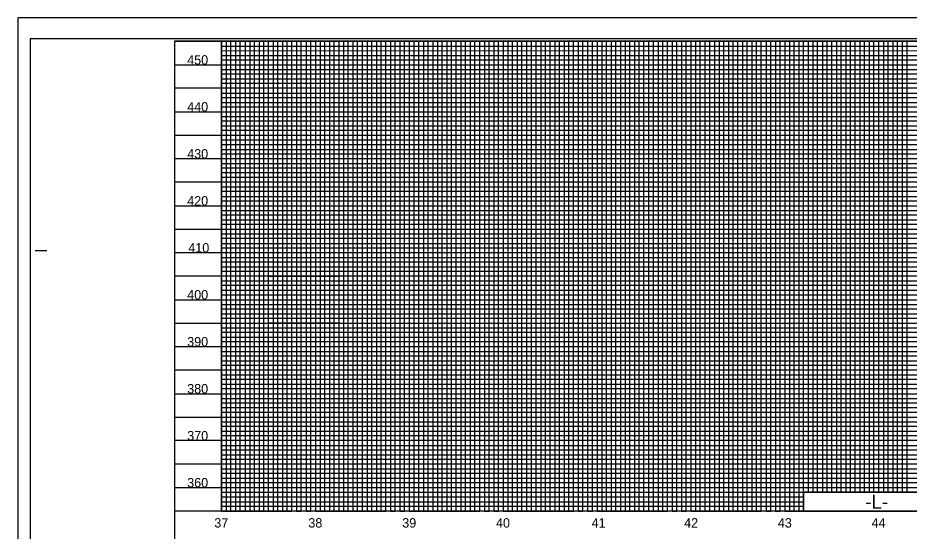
# Model space of a CAD drawing. Extents: x 1632687 to 1634895, y 1174336 to 1175436.
# Drawn here: x 1632687 to 1633637, y 1174889 to 1175436 of the extents above; entities that cross this region are included whole.
import ezdxf

# ---------------------------------------------------------------- set-up
doc = ezdxf.new("R2010")
doc.units = 0
for name, color, linetype in [('Exist Vertical Profile Horizontal Axis Label Major', 7, 'Continuous'), ('Exist Vertical Profile Vertical Axis Label', 7, 'Continuous'), ('Prop Grid Mask', 7, 'Continuous'), ('Sheet Data Field CELL', 7, 'Continuous'), ('Sheet Layout Profile Border Port 1', 7, 'Continuous'), ('Sheet Plot Border Inside CELL', 7, 'Continuous'), ('Sheet Plot Border Outside CELL', 7, 'Continuous'), ('Sheet Profile CELL', 7, 'Continuous'), ('Sheet Profile Grid Major CELL', 7, 'Continuous'), ('Sheet Profile Grid Middle CELL', 7, 'Continuous'), ('Sheet Profile Grid Minor CELL', 7, 'Continuous')]:
    doc.layers.add(name, color=color, linetype=linetype)

msp = doc.modelspace()

# ---------------------------------------------------------------- linework, layer by layer
at = {"layer": 'Prop Grid Mask'}
msp.add_lwpolyline([(1632954.31, 1175160.79), (1633029.31, 1175160.79), (1633029.31, 1175110.79), (1632954.31, 1175110.79)], close=True, dxfattribs=at)
at = {"layer": 'Sheet Data Field CELL'}
msp.add_lwpolyline([(1633524.31, 1174910.79), (1633684.31, 1174910.79), (1633684.31, 1174930.79), (1633524.31, 1174930.79)], close=True, dxfattribs=at)
at = {"layer": 'Sheet Layout Profile Border Port 1'}
msp.add_lwpolyline([(1632904.31, 1175410.79), (1633954.21, 1175410.79), (1633954.21, 1175384.53), (1634154.26, 1175384.53), (1634154.26, 1175249.74), (1634304.31, 1175249.74), (1634304.31, 1174935.79), (1634104.31, 1174935.79), (1634104.31, 1174910.79), (1633684.31, 1174910.79), (1633684.31, 1174930.79), (1633524.31, 1174930.79), (1633524.31, 1174910.79), (1632904.31, 1174910.79)], close=True, dxfattribs=at)
at = {"layer": 'Sheet Plot Border Inside CELL'}
msp.add_lwpolyline([(1632700.31, 1174358.24), (1634366.81, 1174358.24), (1634366.81, 1175413.34), (1632700.31, 1175413.34)], close=True, dxfattribs=at)
at = {"layer": 'Sheet Plot Border Outside CELL'}
msp.add_lwpolyline([(1632687.31, 1174335.79), (1634371.31, 1174335.79), (1634371.31, 1175435.79), (1632687.31, 1175435.79)], close=True, dxfattribs=at)
at = {"layer": 'Sheet Profile CELL'}
for p, q in [((1632705.81, 1175188.29), (1632718.31, 1175188.29)), ((1634354.31, 1174910.79), (1632854.31, 1174910.79))]:
    msp.add_line(p, q, dxfattribs=at)
msp.add_lwpolyline([(1634354.31, 1175410.79), (1632854.31, 1175410.79), (1632854.31, 1174360.79), (1634354.31, 1174360.79)], close=True, dxfattribs=at)
at = {"layer": 'Sheet Profile Grid Major CELL'}
for p, q in [((1632904.31, 1175410.79), (1632904.31, 1174910.79)), ((1632954.31, 1174910.79), (1632954.31, 1175410.79)), ((1632954.31, 1175410.79), (1633004.31, 1175410.79)), ((1633004.31, 1175410.79), (1633004.31, 1174910.79)), ((1633054.31, 1174910.79), (1633054.31, 1175410.79)), ((1633054.31, 1175410.79), (1633104.31, 1175410.79)), ((1633104.31, 1175410.79), (1633104.31, 1174910.79)), ((1633154.31, 1174910.79), (1633154.31, 1175410.79)), ((1633154.31, 1175410.79), (1633204.31, 1175410.79)), ((1633204.31, 1175410.79), (1633204.31, 1174910.79)), ((1633254.31, 1174910.79), (1633254.31, 1175410.79)), ((1633254.31, 1175410.79), (1633304.31, 1175410.79)), ((1633304.31, 1175410.79), (1633304.31, 1174910.79)), ((1633354.31, 1174910.79), (1633354.31, 1175410.79)), ((1633354.31, 1175410.79), (1633404.31, 1175410.79)), ((1633404.31, 1175410.79), (1633404.31, 1174910.79)), ((1633454.31, 1174910.79), (1633454.31, 1175410.79)), ((1633454.31, 1175410.79), (1633504.31, 1175410.79)), ((1633504.31, 1175410.79), (1633504.31, 1174910.79)), ((1633554.31, 1174930.79), (1633554.31, 1175410.79)), ((1633554.31, 1175410.79), (1633604.31, 1175410.79)), ((1633604.31, 1175410.79), (1633604.31, 1174930.79)), ((1632904.31, 1174910.79), (1632954.31, 1174910.79)), ((1633004.31, 1174910.79), (1633054.31, 1174910.79)), ((1633104.31, 1174910.79), (1633154.31, 1174910.79)), ((1633204.31, 1174910.79), (1633254.31, 1174910.79)), ((1633304.31, 1174910.79), (1633354.31, 1174910.79)), ((1633404.31, 1174910.79), (1633454.31, 1174910.79)), ((1633504.31, 1174910.79), (1633534.31, 1174910.79))]:
    msp.add_line(p, q, dxfattribs=at)
for points in [[(1632854.31, 1175385.79), (1633954.21, 1175385.79)], [(1632854.31, 1175335.79), (1634154.26, 1175335.79)], [(1634154.26, 1175285.79), (1632854.31, 1175285.79), (1632854.31, 1175235.79), (1634354.31, 1175235.79)], [(1634354.31, 1175185.79), (1632854.31, 1175185.79), (1632854.31, 1175135.79), (1634354.31, 1175135.79)], [(1634354.31, 1175085.79), (1632854.31, 1175085.79), (1632854.31, 1175035.79), (1634354.31, 1175035.79)], [(1634354.31, 1174985.79), (1632854.31, 1174985.79), (1632854.31, 1174985.79), (1632854.31, 1174935.79), (1634354.31, 1174935.79)]]:
    msp.add_lwpolyline(points, dxfattribs=at)
at = {"layer": 'Sheet Profile Grid Middle CELL'}
msp.add_line((1632854.31, 1175410.79), (1633954.21, 1175410.79), dxfattribs=at)
for points in [[(1632929.31, 1175410.79), (1632929.31, 1174910.79), (1632979.31, 1174910.79), (1632979.31, 1175410.79), (1633029.31, 1175410.79), (1633029.31, 1174910.79), (1633079.31, 1174910.79), (1633079.31, 1175410.79), (1633129.31, 1175410.79), (1633129.31, 1174910.79), (1633179.31, 1174910.79), (1633179.31, 1175410.79), (1633229.31, 1175410.79), (1633229.31, 1174910.79), (1633279.31, 1174910.79), (1633279.31, 1175410.79), (1633329.31, 1175410.79), (1633329.31, 1174910.79), (1633379.31, 1174910.79), (1633379.31, 1175410.79), (1633429.31, 1175410.79), (1633429.31, 1174910.79), (1633479.31, 1174910.79), (1633479.31, 1174910.79), (1633479.31, 1175410.79), (1633529.31, 1175410.79), (1633529.31, 1174930.79)], [(1633579.31, 1174930.79), (1633579.31, 1175410.79), (1633629.31, 1175410.79), (1633629.31, 1174930.79)], [(1634154.26, 1175360.79), (1632854.31, 1175360.79), (1632854.31, 1175310.79), (1634154.26, 1175310.79)], [(1634154.26, 1175260.79), (1632854.31, 1175260.79), (1632854.31, 1175210.79), (1634354.31, 1175210.79)], [(1634354.31, 1175160.79), (1632854.31, 1175160.79), (1632854.31, 1175110.79), (1634354.31, 1175110.79)], [(1634354.31, 1175060.79), (1632854.31, 1175060.79), (1632854.31, 1175010.79), (1634354.31, 1175010.79)], [(1634354.31, 1174960.79), (1632854.31, 1174960.79)]]:
    msp.add_lwpolyline(points, dxfattribs=at)
at = {"layer": 'Sheet Profile Grid Minor CELL'}
for p, q in [((1632904.31, 1175405.79), (1633954.21, 1175405.79)), ((1633434.31, 1175410.79), (1633434.31, 1174910.79)), ((1633439.31, 1174910.79), (1633439.31, 1175410.79)), ((1633439.31, 1175410.79), (1633444.31, 1175410.79)), ((1633444.31, 1175410.79), (1633444.31, 1174910.79)), ((1633449.31, 1174910.79), (1633449.31, 1175410.79)), ((1633449.31, 1175410.79), (1633459.31, 1175410.79)), ((1633459.31, 1175410.79), (1633459.31, 1174910.79)), ((1633464.31, 1174910.79), (1633464.31, 1175410.79)), ((1633464.31, 1175410.79), (1633469.31, 1175410.79)), ((1633469.31, 1175410.79), (1633469.31, 1174910.79)), ((1633474.31, 1174910.79), (1633474.31, 1175410.79)), ((1633474.31, 1175410.79), (1633484.31, 1175410.79)), ((1633484.31, 1175410.79), (1633484.31, 1174910.79)), ((1633489.31, 1174910.79), (1633489.31, 1175410.79)), ((1633489.31, 1175410.79), (1633494.31, 1175410.79)), ((1633494.31, 1175410.79), (1633494.31, 1174910.79)), ((1633499.31, 1174910.79), (1633499.31, 1175410.79)), ((1633499.31, 1175410.79), (1633509.31, 1175410.79)), ((1633509.31, 1175410.79), (1633509.31, 1174910.79)), ((1633514.31, 1174910.79), (1633514.31, 1175410.79)), ((1633514.31, 1175410.79), (1633519.31, 1175410.79)), ((1633519.31, 1175410.79), (1633519.31, 1174910.79)), ((1633524.31, 1174910.79), (1633524.31, 1175410.79)), ((1633524.31, 1175410.79), (1633534.31, 1175410.79)), ((1633534.31, 1175410.79), (1633534.31, 1174930.79)), ((1633539.31, 1174930.79), (1633539.31, 1175410.79)), ((1633539.31, 1175410.79), (1633544.31, 1175410.79)), ((1633544.31, 1175410.79), (1633544.31, 1174930.79)), ((1633549.31, 1174930.79), (1633549.31, 1175410.79)), ((1633549.31, 1175410.79), (1633559.31, 1175410.79)), ((1633559.31, 1175410.79), (1633559.31, 1174930.79)), ((1632904.31, 1175400.79), (1632904.31, 1175400.79)), ((1633954.21, 1175400.73), (1632904.31, 1175400.44)), ((1632904.31, 1175395.79), (1633954.21, 1175395.79)), ((1634154.31, 1175275.79), (1632904.31, 1175275.79)), ((1634154.31, 1175270.79), (1632904.31, 1175270.79)), ((1634154.31, 1175265.79), (1632904.31, 1175265.79)), ((1632904.31, 1175255.79), (1634154.31, 1175255.79)), ((1634154.31, 1175250.79), (1632904.31, 1175250.79)), ((1632904.31, 1175245.79), (1634304.31, 1175245.79)), ((1634304.31, 1175225.79), (1632904.31, 1175225.79)), ((1632904.31, 1175220.79), (1634304.31, 1175220.79)), ((1634304.31, 1175200.79), (1632904.31, 1175200.79)), ((1632904.31, 1175195.79), (1634304.31, 1175195.79)), ((1634304.31, 1175175.79), (1632904.31, 1175175.79)), ((1632904.31, 1175170.79), (1634304.31, 1175170.79)), ((1634304.31, 1175165.79), (1632904.31, 1175165.79)), ((1632904.31, 1175155.79), (1634304.31, 1175155.79)), ((1634304.31, 1175150.79), (1632904.31, 1175150.79)), ((1632904.31, 1175145.79), (1634304.31, 1175145.79)), ((1634304.31, 1175140.79), (1632904.31, 1175140.79)), ((1632904.31, 1175130.79), (1634304.31, 1175130.79)), ((1634304.31, 1175125.79), (1632904.31, 1175125.79)), ((1632904.31, 1175120.79), (1634304.31, 1175120.79)), ((1634304.31, 1175115.79), (1632904.31, 1175115.79)), ((1632904.31, 1175105.79), (1634304.31, 1175105.79)), ((1634304.31, 1175100.79), (1632904.31, 1175100.79)), ((1632904.31, 1175095.79), (1634304.31, 1175095.79)), ((1634304.31, 1175090.79), (1632904.31, 1175090.79)), ((1632904.31, 1175080.79), (1634304.31, 1175080.79)), ((1634304.31, 1175075.79), (1632904.31, 1175075.79)), ((1632904.31, 1175070.79), (1634304.31, 1175070.79)), ((1634304.31, 1175065.79), (1632904.31, 1175065.79)), ((1632904.31, 1175055.79), (1634304.31, 1175055.79)), ((1634304.31, 1175050.79), (1632904.31, 1175050.79)), ((1632904.31, 1175045.79), (1634304.31, 1175045.79)), ((1634304.31, 1175040.79), (1632904.31, 1175040.79)), ((1632904.31, 1175030.79), (1634304.31, 1175030.79)), ((1634304.31, 1175025.79), (1632904.31, 1175025.79)), ((1634304.31, 1175020.79), (1632904.31, 1175020.79)), ((1634304.31, 1175015.79), (1632904.31, 1175015.79)), ((1632904.31, 1175005.79), (1634304.31, 1175005.79)), ((1634304.31, 1175000.79), (1632904.31, 1175000.79)), ((1632904.31, 1174995.79), (1634304.31, 1174995.79)), ((1634304.31, 1174990.79), (1632904.31, 1174990.79)), ((1632904.31, 1174980.79), (1634304.31, 1174980.79)), ((1634304.31, 1174975.79), (1632904.31, 1174975.79)), ((1632904.31, 1174970.79), (1634304.31, 1174970.79)), ((1634304.31, 1174965.79), (1632904.31, 1174965.79)), ((1632904.31, 1174955.79), (1634304.31, 1174955.79)), ((1634304.31, 1174950.79), (1632904.31, 1174950.79)), ((1632904.31, 1174945.79), (1634304.31, 1174945.79)), ((1634304.31, 1174940.79), (1632904.31, 1174940.79)), ((1632904.31, 1174930.79), (1634104.31, 1174930.79)), ((1633524.31, 1174925.79), (1632904.31, 1174925.79)), ((1632904.31, 1174920.79), (1633524.31, 1174920.79)), ((1633434.31, 1174910.79), (1633439.31, 1174910.79)), ((1633444.31, 1174910.79), (1633449.31, 1174910.79)), ((1633459.31, 1174910.79), (1633464.31, 1174910.79)), ((1633469.31, 1174910.79), (1633474.31, 1174910.79)), ((1633484.31, 1174910.79), (1633489.31, 1174910.79)), ((1633494.31, 1174910.79), (1633499.31, 1174910.79)), ((1633509.31, 1174910.79), (1633514.31, 1174910.79)), ((1633519.31, 1174910.79), (1633524.31, 1174910.79)), ((1633534.31, 1174910.79), (1633539.31, 1174910.79)), ((1633544.31, 1174910.79), (1633549.31, 1174910.79))]:
    msp.add_line(p, q, dxfattribs=at)
for points in [[(1632909.31, 1175410.79), (1632909.31, 1174910.79), (1632914.31, 1174910.79), (1632914.31, 1175410.79), (1632919.31, 1175410.79), (1632919.31, 1174910.79), (1632924.31, 1174910.79), (1632924.31, 1175410.79), (1632934.31, 1175410.79), (1632934.31, 1174910.79), (1632939.31, 1174910.79), (1632939.31, 1175410.79), (1632944.31, 1175410.79), (1632944.31, 1174910.79), (1632949.31, 1174910.79), (1632959.31, 1174910.79), (1632964.31, 1174910.79), (1632964.31, 1175410.79), (1632969.31, 1175410.79), (1632969.31, 1174910.79), (1632974.31, 1174910.79), (1632974.31, 1175410.79), (1632984.31, 1175410.79), (1632984.31, 1174910.79), (1632989.31, 1174910.79), (1632989.31, 1175410.79), (1632994.31, 1175410.79), (1632994.31, 1174910.79), (1632999.31, 1174910.79), (1632999.31, 1175410.79), (1633009.31, 1175410.79), (1633009.31, 1174910.79), (1633014.31, 1174910.79), (1633014.31, 1175410.79), (1633019.31, 1175410.79), (1633019.31, 1174910.79), (1633024.31, 1174910.79), (1633024.31, 1175410.79), (1633034.31, 1175410.79), (1633034.31, 1174910.79), (1633039.31, 1174910.79), (1633039.31, 1175410.79), (1633044.31, 1175410.79), (1633044.31, 1174910.79), (1633049.31, 1174910.79), (1633049.31, 1175410.79), (1633059.31, 1175410.79), (1633059.31, 1174910.79), (1633064.31, 1174910.79), (1633064.31, 1175410.79), (1633069.31, 1175410.79), (1633069.31, 1174910.79), (1633074.31, 1174910.79), (1633074.31, 1175410.79), (1633084.31, 1175410.79), (1633084.31, 1174910.79), (1633089.31, 1174910.79), (1633089.31, 1175410.79), (1633094.31, 1175410.79), (1633094.31, 1174910.79), (1633099.31, 1174910.79), (1633099.31, 1175410.79), (1633109.31, 1175410.79), (1633109.31, 1174910.79), (1633114.31, 1174910.79), (1633114.31, 1175410.79), (1633119.31, 1175410.79), (1633119.31, 1174910.79)], [(1632949.31, 1174910.79), (1632949.31, 1175410.79), (1632959.31, 1175410.79), (1632959.31, 1174910.79)], [(1633119.31, 1174910.79), (1633124.31, 1174910.79), (1633124.31, 1175410.79), (1633134.31, 1175410.79), (1633134.31, 1174910.79), (1633139.31, 1174910.79), (1633139.31, 1175410.79), (1633144.31, 1175410.79), (1633144.31, 1174910.79), (1633149.31, 1174910.79), (1633149.31, 1175410.79), (1633159.31, 1175410.79), (1633159.31, 1174910.79), (1633164.31, 1174910.79), (1633164.31, 1175410.79), (1633169.31, 1175410.79), (1633169.31, 1174910.79), (1633174.31, 1174910.79), (1633174.31, 1175410.79), (1633184.31, 1175410.79), (1633184.31, 1174910.79), (1633189.31, 1174910.79), (1633189.31, 1175410.79), (1633194.31, 1175410.79), (1633194.31, 1174910.79), (1633199.31, 1174910.79), (1633199.31, 1175410.79), (1633209.31, 1175410.79), (1633209.31, 1174910.79), (1633214.31, 1174910.79), (1633214.31, 1175410.79), (1633219.31, 1175410.79), (1633219.31, 1174910.79), (1633224.31, 1174910.79), (1633224.31, 1175410.79), (1633234.31, 1175410.79), (1633234.31, 1174910.79), (1633239.31, 1174910.79), (1633239.31, 1175410.79), (1633244.31, 1175410.79), (1633244.31, 1174910.79), (1633249.31, 1174910.79), (1633249.31, 1175410.79), (1633259.31, 1175410.79), (1633259.31, 1174910.79), (1633264.31, 1174910.79), (1633264.31, 1175410.79), (1633269.31, 1175410.79), (1633269.31, 1174910.79), (1633274.31, 1174910.79), (1633274.31, 1175410.79), (1633284.31, 1175410.79), (1633284.31, 1174910.79), (1633289.31, 1174910.79), (1633289.31, 1175410.79), (1633294.31, 1175410.79), (1633294.31, 1174910.79), (1633299.31, 1174910.79), (1633299.31, 1175410.79), (1633309.31, 1175410.79), (1633309.31, 1174910.79), (1633314.31, 1174910.79), (1633314.31, 1175410.79), (1633319.31, 1175410.79), (1633319.31, 1174910.79), (1633324.31, 1174910.79), (1633324.31, 1175410.79), (1633334.31, 1175410.79), (1633334.31, 1174910.79), (1633339.31, 1174910.79), (1633339.31, 1175410.79), (1633344.31, 1175410.79), (1633344.31, 1174910.79), (1633349.31, 1174910.79), (1633349.31, 1175410.79), (1633359.31, 1175410.79), (1633359.31, 1174910.79), (1633364.31, 1174910.79), (1633364.31, 1175410.79), (1633369.31, 1175410.79), (1633369.31, 1174910.79), (1633374.31, 1174910.79), (1633374.31, 1175410.79), (1633384.31, 1175410.79), (1633384.31, 1174910.79), (1633389.31, 1174910.79), (1633389.31, 1175410.79), (1633394.31, 1175410.79), (1633394.31, 1174910.79), (1633399.31, 1174910.79), (1633399.31, 1175410.79), (1633409.31, 1175410.79), (1633409.31, 1174910.79), (1633414.31, 1174910.79), (1633414.31, 1175410.79), (1633419.31, 1175410.79), (1633419.31, 1174910.79), (1633424.31, 1174910.79), (1633424.31, 1175410.79), (1633434.31, 1175410.79)], [(1633564.31, 1174930.79), (1633564.31, 1175410.79), (1633569.31, 1175410.79), (1633569.31, 1174930.79)], [(1633574.31, 1174930.79), (1633574.31, 1175410.79), (1633584.31, 1175410.79), (1633584.31, 1174930.79)], [(1633589.31, 1174930.79), (1633589.31, 1175410.79), (1633594.31, 1175410.79), (1633594.31, 1174930.79)], [(1633599.31, 1174930.79), (1633599.31, 1175410.79), (1633609.31, 1175410.79), (1633609.31, 1174930.79)], [(1633614.31, 1174930.79), (1633614.31, 1175410.79), (1633619.31, 1175410.79), (1633619.31, 1174930.79)], [(1633624.31, 1174930.79), (1633624.31, 1175410.79), (1633634.31, 1175410.79), (1633634.31, 1174930.79)], [(1633954.21, 1175390.79), (1632904.31, 1175390.79), (1632904.31, 1175380.79), (1634154.26, 1175380.79)], [(1634154.26, 1175375.79), (1632904.31, 1175375.79), (1632904.31, 1175370.79), (1634154.26, 1175370.79)], [(1634154.26, 1175365.79), (1632904.31, 1175365.79), (1632904.31, 1175355.79), (1634154.26, 1175355.79)], [(1634154.26, 1175350.79), (1632904.31, 1175350.79), (1632904.31, 1175345.79), (1634154.26, 1175345.79)], [(1634154.26, 1175340.79), (1632904.31, 1175340.79), (1632904.31, 1175330.79), (1634154.26, 1175330.79)], [(1634154.26, 1175325.79), (1632904.31, 1175325.79), (1632904.31, 1175320.79), (1634154.26, 1175320.79)], [(1634154.26, 1175315.79), (1632904.31, 1175315.79), (1632904.31, 1175305.79), (1634154.26, 1175305.79)], [(1634154.26, 1175300.69), (1632904.41, 1175300.69), (1632904.41, 1175295.79), (1634154.26, 1175295.79)], [(1634154.26, 1175290.79), (1632904.31, 1175290.79), (1632904.31, 1175280.79), (1634154.26, 1175280.79)], [(1634304.31, 1175240.79), (1632904.31, 1175240.79), (1632904.31, 1175230.79), (1634304.31, 1175230.79)], [(1634304.31, 1175215.79), (1632904.31, 1175215.79), (1632904.31, 1175205.79), (1634304.31, 1175205.79)], [(1634304.31, 1175190.79), (1632904.31, 1175190.79), (1632904.31, 1175180.79), (1634304.31, 1175180.79)], [(1633524.31, 1174915.79), (1632904.31, 1174915.79)]]:
    msp.add_lwpolyline(points, dxfattribs=at)

# ---------------------------------------------------------------- texts
at = {"layer": 'Exist Vertical Profile Horizontal Axis Label Major'}
for s, p in [('37', (1632896.66, 1174893.29)), ('38', (1632996.78, 1174893.29)), ('39', (1633096.82, 1174893.29)), ('40', (1633196.7, 1174893.29)), ('41', (1633298.54, 1174893.29)), ('42', (1633397.09, 1174893.29)), ('43', (1633496.92, 1174893.29)), ('44', (1633596.77, 1174893.29))]:
    msp.add_text(s, height=10, dxfattribs=at).set_placement(p)
at = {"layer": 'Exist Vertical Profile Vertical Axis Label'}
for s, p in [('450', (1632867.75, 1175386.04)), ('440', (1632867.75, 1175336.04)), ('430', (1632867.75, 1175286.04)), ('420', (1632867.75, 1175236.04)), ('410', (1632868.94, 1175186.04)), ('400', (1632867.75, 1175136.04)), ('390', (1632867.75, 1175086.04)), ('380', (1632867.75, 1175036.04)), ('370', (1632867.75, 1174986.04)), ('360', (1632867.75, 1174936.04))]:
    msp.add_text(s, height=10, dxfattribs=at).set_placement(p)
at = {"layer": 'Sheet Data Field CELL'}
msp.add_text('-L-', height=15, rotation=360, dxfattribs=at).set_placement((1633589.88, 1174913.29))

doc.saveas('drawing.dxf')
